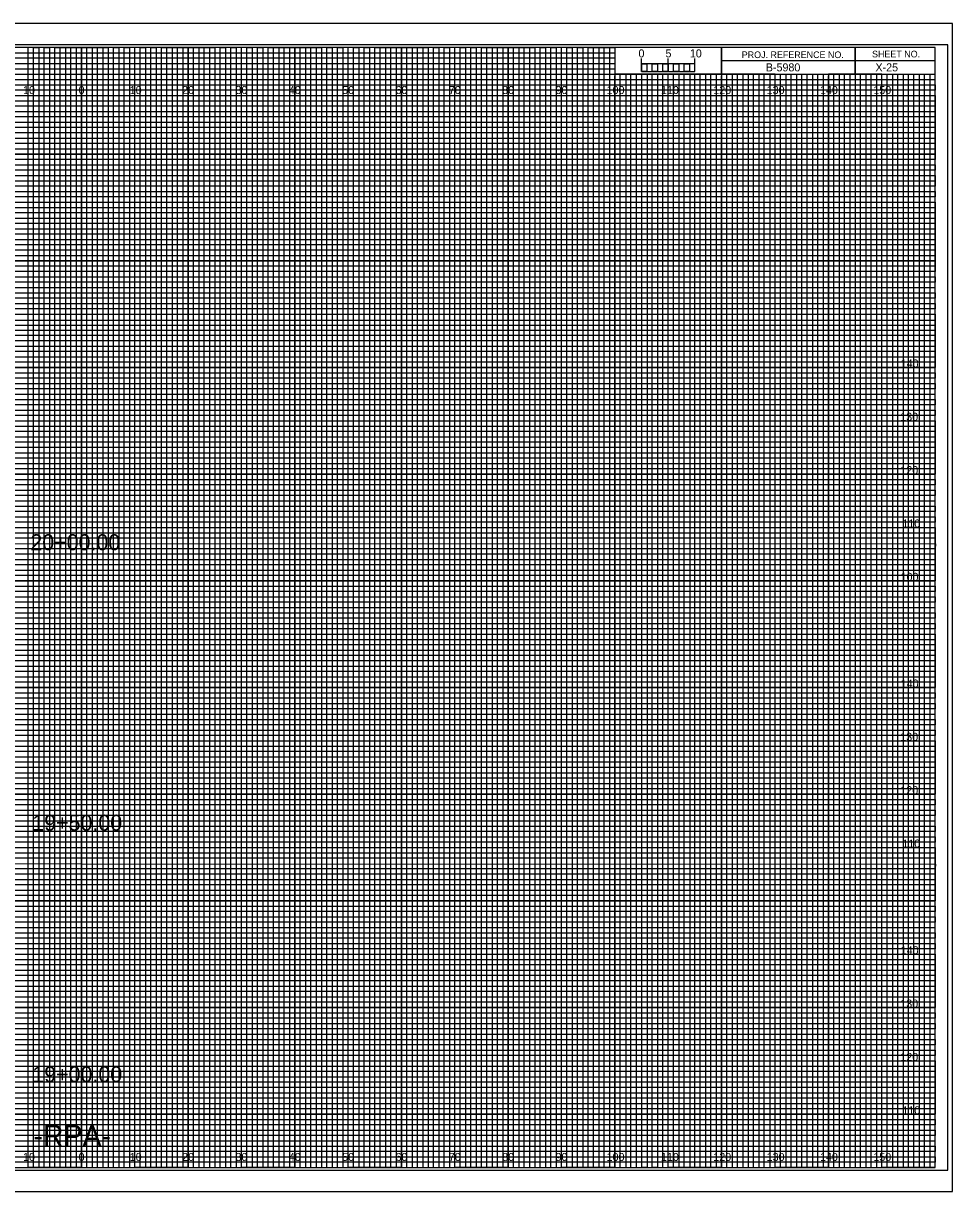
# Model space of a CAD drawing. Extents: x -13 to 323, y -5 to 1974.
# Drawn here: x 149.1 to 323.3, y 215.5 to 434.5 of the extents above; entities that cross this region are included whole.
import ezdxf

# ---------------------------------------------------------------- set-up
doc = ezdxf.new("R2010")
doc.units = 0
for name, color, linetype in [('Exist Cross Section Cell', 7, 'Continuous'), ('Exist XS Center Line Elevation Label', 7, 'Continuous'), ('Exist XS Ground Line', 7, 'Continuous'), ('Prop CMT Bridge Girder Bottom Critical Point Inside', 7, 'Continuous'), ('Prop CMT Guardrail Graphics', 7, 'Continuous'), ('Prop CMT Guardrail Widen Shoulder', 7, 'Continuous'), ('Prop CMT Pvmt Course 1', 7, 'Continuous'), ('Prop CMT Pvmt Course 2', 7, 'Continuous'), ('Prop CMT Pvmt Course 3', 7, 'Continuous'), ('Prop CMT Pvmt Surface', 7, 'Continuous'), ('Prop CMT Pvmt Surface Shoulder', 7, 'Continuous'), ('Prop CMT Shld Paved Course 1', 7, 'Continuous'), ('Prop CMT Shld Paved Course 2', 7, 'Continuous'), ('Prop CMT Shld Paved Course 3', 7, 'Continuous'), ('Prop CMT Slope Grass', 7, 'Continuous'), ('Prop CMT Subgrade Earthwork', 7, 'Continuous'), ('Scratch_Level_1', 7, 'Continuous')]:
    doc.layers.add(name, color=color, linetype=linetype)

msp = doc.modelspace()

# ---------------------------------------------------------------- linework, layer by layer
at = {"layer": 'Exist XS Center Line Elevation Label'}
for points in [[(145, 220), (155, 220), (155, 430), (165, 430), (165, 220), (175, 220), (175, 430), (185, 430), (185, 220), (195, 220), (195, 430), (205, 430), (205, 220), (215, 220), (215, 430), (225, 430), (225, 220), (235, 220), (235, 430), (245, 430), (245, 220), (255, 220), (255, 430), (259.93, 430), (260, 430), (260, 425), (264.99, 425), (264.99, 220), (275, 220), (275, 425), (285, 425), (285, 220), (295, 220), (295, 425), (305, 425), (305, 220), (315, 220), (315, 425)], [(0, 425), (275, 425)], [(0, 405), (320, 405), (320, 415), (0, 415)], [(0, 385), (320, 385), (320, 395), (0, 395)], [(0, 365), (320, 365), (320, 375), (0, 375)], [(0, 345), (320, 345), (320, 355), (0, 355)], [(0, 325), (320, 325), (320, 335), (0, 335)], [(0, 305), (320, 305), (320, 315), (0, 315)], [(0, 285), (320, 285), (320, 295), (0, 295)], [(0, 265), (320, 265), (320, 275), (0, 275)], [(0, 245), (320, 245), (320, 255), (0, 255)], [(0, 225), (320, 225), (320, 235), (0, 235)]]:
    msp.add_lwpolyline(points, dxfattribs=at)
at = {"layer": 'Exist XS Ground Line'}
for p, q in [((150, 430), (140, 430)), ((150, 220), (150, 430)), ((170, 430), (160, 430)), ((160, 430), (160, 220)), ((170, 220), (170, 430)), ((190, 430), (180, 430)), ((180, 430), (180, 220)), ((190, 220), (190, 430)), ((210, 430), (200, 430)), ((200, 430), (200, 220)), ((210, 220), (210, 430)), ((230, 430), (220, 430)), ((220, 430), (220, 220)), ((230, 220), (230, 430)), ((250, 430), (240, 430)), ((240, 430), (240, 220)), ((250, 220), (250, 430)), ((260, 430), (260, 220)), ((270, 220), (270, 425)), ((290, 425), (280, 425)), ((280, 425), (280, 220)), ((290, 220), (290, 425)), ((310, 425), (300, 425)), ((300, 425), (300, 220)), ((310, 220), (310, 425)), ((160, 220), (150, 220)), ((180, 220), (170, 220)), ((200, 220), (190, 220)), ((220, 220), (210, 220)), ((240, 220), (230, 220)), ((260, 220), (250, 220)), ((280, 220), (270, 220)), ((300, 220), (290, 220)), ((320, 220), (310, 220)), ((320, 220), (320, 220))]:
    msp.add_line(p, q, dxfattribs=at)
for points in [[(0, 420), (320, 420), (320, 410), (0, 410)], [(0, 400), (320, 400), (320, 390), (0, 390)], [(0, 380), (320, 380), (320, 370), (0, 370)], [(0, 360), (320, 360), (320, 350), (0, 350)], [(0, 340), (320, 340), (320, 330), (0, 330)], [(0, 320), (320, 320), (320, 310), (0, 310)], [(0, 300), (320, 300), (320, 290), (0, 290)], [(0, 280), (320, 280), (320, 270), (0, 270)], [(0, 260), (320, 260), (320, 250), (0, 250)], [(0, 240), (320, 240), (320, 230), (0, 230)]]:
    msp.add_lwpolyline(points, dxfattribs=at)
at = {"layer": 'Prop CMT Pvmt Course 2'}
for p, q in [((265, 425.49), (265, 427.9)), ((265, 426.9), (265, 427.9)), ((270, 425.49), (270, 427.9)), ((275, 425.49), (275, 427.9)), ((275, 426.9), (275, 427.9))]:
    msp.add_line(p, q, dxfattribs=at)
for points in [[(275, 426.9), (265, 426.9), (265, 425.49), (275, 425.49)], [(265, 426.9), (266, 426.9), (266, 425.49), (265, 425.49)], [(267, 426.9), (268, 426.9), (268, 425.49), (267, 425.49)], [(269, 426.9), (270, 426.9), (270, 425.49), (269, 425.49)], [(271, 426.9), (272, 426.9), (272, 425.49), (271, 425.49)], [(273, 426.9), (274, 426.9), (274, 425.49), (273, 425.49)]]:
    msp.add_lwpolyline(points, close=True, dxfattribs=at)
at = {"layer": 'Prop CMT Pvmt Course 3'}
msp.add_lwpolyline([(-13.4, 215.5), (323.3, 215.5), (323.3, 434.5), (-13.4, 434.5)], close=True, dxfattribs=at)
at = {"layer": 'Prop CMT Pvmt Surface'}
for p, q in [((150, 220), (150, 430)), ((160, 220), (160, 430)), ((170, 220), (170, 430)), ((180, 220), (180, 430)), ((190, 220), (190, 430)), ((200, 220), (200, 430)), ((210, 220), (210, 430)), ((220, 220), (220, 430)), ((230, 220), (230, 430)), ((240, 220), (240, 430)), ((250, 220), (250, 430)), ((260, 220), (260, 424.69)), ((270, 220), (270, 424.69)), ((280, 220), (280, 424.69)), ((290, 220), (290, 424.69)), ((300, 220), (300, 424.69)), ((310, 220), (310, 424.69)), ((0, 420), (320, 420)), ((0, 410), (320, 410)), ((0, 400), (320, 400)), ((0, 390), (320, 390)), ((0, 380), (320, 380)), ((0, 370), (320, 370)), ((0, 360), (320, 360)), ((0, 350), (320, 350)), ((0, 340), (320, 340)), ((0, 330), (320, 330)), ((0, 320), (320, 320)), ((0, 310), (320, 310)), ((0, 300), (320, 300)), ((0, 290), (320, 290)), ((0, 280), (320, 280)), ((0, 270), (320, 270)), ((0, 260), (320, 260)), ((0, 250), (320, 250)), ((0, 240), (320, 240)), ((0, 230), (320, 230))]:
    msp.add_line(p, q, dxfattribs=at)
at = {"layer": 'Prop CMT Pvmt Surface Shoulder'}
for p, q in [((323.3, 434.5), (-13.4, 434.5)), ((-13.4, 215.5), (323.3, 215.5))]:
    msp.add_line(p, q, dxfattribs=at)
at = {"layer": 'Prop CMT Shld Paved Course 1'}
for p, q in [((0, 429), (260, 429)), ((260, 427.98), (0, 427.98)), ((260, 429), (260, 427.98)), ((0, 427), (260, 427)), ((260, 425.89), (0, 425.89)), ((260, 427), (260, 425.89)), ((0, 424), (320, 424))]:
    msp.add_line(p, q, dxfattribs=at)
for points in [[(0, 423), (270, 423), (320, 423), (320, 422), (0, 422)], [(0, 421), (320, 421), (320, 419), (0, 419)], [(0, 418), (320, 418), (320, 417), (0, 416.98)], [(0, 416), (320, 416), (320, 414), (0, 414)], [(0, 413), (320, 413), (320, 412), (0, 412)], [(0, 411), (320, 411), (320, 409), (0, 409)], [(0, 408), (320, 408), (320, 407), (0, 407)], [(0, 406), (320, 406), (320, 404), (0, 404)], [(0, 403), (320, 403), (320, 402), (0, 402)], [(0, 401), (320, 401), (320, 399), (0, 399)], [(0, 398), (320, 398), (320, 397), (0, 397)], [(0, 396), (320, 396), (320, 393.95), (320, 393), (320, 392), (0, 392)], [(0, 394), (320, 394), (320, 393), (0, 393)], [(0, 391), (320, 391), (320, 389), (0, 389.03)], [(0, 389.03), (320, 389), (320, 388), (0, 388)], [(0, 387), (320, 387), (320, 386), (0, 386)], [(0, 384), (320, 384), (320, 383), (0, 383)], [(0, 382), (320, 382), (320, 381), (0, 381)], [(-0.07, 378.89), (320, 378.89), (320, 377.88), (-0.07, 377.88)], [(0, 377), (320, 377), (320, 376), (0, 376)], [(0, 374), (320, 374), (320, 373), (0, 373)], [(0, 372), (320, 372), (320, 371), (0, 371)], [(0, 369), (320, 369), (320, 368), (0, 368)], [(0, 367), (320, 367), (320, 366), (0, 366)], [(0, 364), (320, 364), (320, 363), (0, 363)], [(0, 362), (320, 362), (320, 361), (0, 361)], [(0, 359), (320, 359), (319.99, 357.98), (0, 358)], [(0, 357), (320, 357), (320, 356), (0, 356)], [(0, 354), (320, 354), (320, 353), (0, 353)], [(0, 352), (320, 352), (320, 351), (0, 351)], [(0, 349), (320, 349), (320, 348), (0, 348)], [(0, 347), (320, 347), (320, 346), (0, 346)], [(0, 344), (320, 344), (320, 343), (0, 343)], [(0, 342), (320, 342), (320, 341), (0, 341)], [(0, 339), (320, 339), (320, 338), (0, 338)], [(0, 336.99), (320.07, 336.91), (320, 336), (0, 336)], [(0, 334), (320, 334), (320, 333), (0, 333)], [(0, 332), (320, 332), (320, 331), (0, 331)], [(0, 329), (320, 329), (320, 328), (0, 328)], [(0, 327), (320, 327), (320, 326), (0, 326)], [(0, 324), (320, 324), (320, 323), (0, 323)], [(0, 322), (320, 322), (320, 321), (0, 321)], [(0, 319), (320, 319), (320, 318), (0, 318)], [(0, 317), (320, 317), (320, 316), (0, 316)], [(0, 314), (320, 314), (320, 313), (0, 313)], [(0, 312), (320, 312), (320, 311), (0, 311)], [(0, 309), (320, 309), (320, 308), (0, 308)], [(0, 307), (320, 307), (320, 306), (0, 306)], [(0, 304), (320, 304), (320, 303), (0, 303)], [(0, 302), (320, 302), (320, 301), (0, 301)], [(0, 299), (320, 299), (319.99, 297.98), (0, 298)], [(0, 297), (320, 297), (320, 296), (0, 296)], [(0, 294), (320, 294), (320, 293), (0, 293)], [(0, 292), (320, 292), (320, 291), (0, 291)], [(0, 289), (320, 289), (320, 288), (0, 288)], [(0, 287), (320, 287), (320, 286), (0, 286)], [(0, 284), (320, 284), (320, 283), (0, 283)], [(0, 282), (320, 282), (320, 281), (0, 281)], [(0, 279), (320, 279), (320, 278), (0, 278)], [(0, 276.99), (320.07, 276.91), (320, 276), (0, 276)], [(0, 274), (320, 274), (320, 273), (0, 273)], [(0, 272), (320, 272), (320, 271), (0, 271)], [(0, 269), (320, 269), (320, 268), (0, 268)], [(0, 267), (320, 267), (320, 266), (0, 266)], [(0, 264), (320, 264), (320, 263), (0, 263)], [(0, 262), (320, 262), (320, 261), (0, 261)], [(0, 259), (320, 259), (320, 258), (0, 258)], [(0, 257), (320, 257), (320, 256), (0, 256)], [(0, 254), (320, 254), (320, 253), (0, 253)], [(0, 252), (320, 252), (320, 251), (0, 251)], [(0, 249), (320, 249), (320, 248), (0, 248)], [(0, 247), (320, 247), (320, 246), (0, 246)], [(0, 244), (320, 244), (320, 243), (0, 243)], [(0, 242), (320, 242), (320, 241), (0, 241)], [(0, 239), (320, 239), (320, 238), (0, 238)], [(0, 237), (320, 237), (320, 236), (0, 236)], [(0, 234), (320, 234), (320, 233), (0, 233)], [(0, 232), (320, 232), (320, 231), (0, 231)], [(0, 229), (320, 229), (320, 228), (0, 228)], [(0, 227), (320, 227), (320, 226), (0, 226)], [(0, 224), (320, 224), (320, 223), (0, 223)], [(0, 222), (320, 222), (320, 221), (0, 221)]]:
    msp.add_lwpolyline(points, dxfattribs=at)
at = {"layer": 'Prop CMT Shld Paved Course 2'}
for p, q in [((305, 430), (305, 425)), ((305, 425), (305, 430)), ((280, 427.5), (280, 425)), ((320, 427.49), (280, 427.49)), ((280, 425), (320, 425))]:
    msp.add_line(p, q, dxfattribs=at)
for points in [[(320, 430), (0, 430), (0, 220), (320, 220)], [(280, 430), (260, 430), (260, 425.03), (280, 425.03)], [(320, 430), (280, 430), (280, 425), (320, 425)]]:
    msp.add_lwpolyline(points, close=True, dxfattribs=at)
at = {"layer": 'Prop CMT Shld Paved Course 3'}
for p, q in [((267, 425), (266.01, 425)), ((266.01, 425), (266.01, 220)), ((267, 220), (267, 425)), ((269, 425), (268, 425)), ((268, 425), (268, 220)), ((269, 220), (269, 425)), ((266.01, 220), (265, 220)), ((268, 220), (267, 220))]:
    msp.add_line(p, q, dxfattribs=at)
for points in [[(150, 220), (151, 220), (151, 430), (152, 430), (152, 220)], [(152, 220), (153, 220), (153, 430), (154, 430), (154, 220)], [(155, 220), (156, 220), (156, 430), (157, 430), (157, 220)], [(157, 220), (158, 220), (158, 430), (159, 430), (159, 220)], [(160, 220), (161, 220), (161, 430), (162, 430), (162, 220)], [(162, 220), (163, 220), (163, 430), (164, 430), (164, 220)], [(165, 220), (166, 220), (166, 430), (167, 430), (167, 220)], [(167, 220), (168, 220), (168, 430), (169, 430), (169, 220)], [(170, 220), (171, 220), (171, 430), (172, 430), (172, 220)], [(172, 220), (173, 220), (173, 430), (174, 430), (174, 220)], [(175, 220), (176, 220), (176, 430), (177, 430), (177, 220)], [(177, 220), (178, 220), (178, 430), (179, 430), (179, 220)], [(180, 220), (181, 220), (181, 430), (182, 430), (182, 220)], [(182, 220), (183, 220), (183, 430), (184, 430), (184, 220)], [(185, 220), (186, 220), (186, 430), (187, 430), (187, 220)], [(187, 220), (188, 220), (188, 430), (189, 430), (189, 220)], [(190, 220), (191, 220), (191, 430), (192, 430), (192, 220)], [(192, 220), (193, 220), (193, 430), (194, 430), (194, 220)], [(195, 220), (196, 220), (196, 430), (197, 430), (197, 220)], [(197, 220), (198, 220), (198, 430), (199, 430), (199, 220)], [(200, 220), (201, 220), (201, 430), (202, 430), (202, 220)], [(202, 220), (203, 220), (203, 430), (204, 430), (204, 220)], [(205, 220), (206, 220), (206, 430), (207, 430), (207, 220)], [(207, 220), (208, 220), (208, 430), (209, 430), (209, 220)], [(210, 220), (211, 220), (211, 430), (212, 430), (212, 220)], [(212, 220), (213, 220), (213, 430), (214, 430), (214, 220)], [(215, 220), (216, 220), (216, 430), (217, 430), (217, 220)], [(217, 220), (218, 220), (218, 430), (219, 430), (219, 220)], [(220, 220), (221, 220), (221, 430), (222, 430), (222, 220)], [(222, 220), (223, 220), (223, 430), (224, 430), (224, 220)], [(225, 220), (226, 220), (226, 430), (227, 430), (227, 220)], [(227, 220), (228, 220), (228, 430), (229, 430), (229, 220)], [(230, 220), (231, 220), (231, 430), (232, 430), (232, 220)], [(232, 220), (233, 220), (233, 430), (234, 430), (234, 220)], [(235, 220), (236, 220), (236, 430), (237, 430), (237, 220)], [(237, 220), (238, 220), (238, 430), (239, 430), (239, 220)], [(240, 220), (241, 220), (241, 430), (242, 430), (242, 220)], [(242, 220), (243, 220), (243, 430), (244, 430), (244, 220)], [(245, 220), (246, 220), (246, 430), (247, 430), (247, 220)], [(247, 220), (248, 220), (248, 430), (249, 430), (249, 220)], [(250, 220), (251, 220), (251, 430), (252, 430), (252, 220)], [(252, 220), (253, 220), (253, 430), (254, 430), (254, 220)], [(255, 220), (256, 220), (256, 430), (257, 430), (257, 220)], [(257, 220), (258, 220), (258, 430), (259, 430), (259, 220)], [(260, 220), (261, 220), (261, 425), (262.02, 425), (262.02, 220)], [(262, 220), (263, 220), (263, 425), (263.99, 425), (263.99, 220)], [(270, 220), (270.98, 220), (270.98, 425), (272, 425), (272, 220)], [(272, 220), (273, 220), (273, 425), (274.05, 425), (274.05, 220)], [(275, 220), (276, 220), (276, 425), (277, 425), (277, 220)], [(277, 220), (278, 220), (278, 425), (279, 425), (279, 220)], [(280, 220), (281, 220), (281, 425), (282, 425), (282, 220)], [(282, 220), (283, 220), (283, 425), (284, 425), (284, 220)], [(285, 220), (286, 220), (286, 425), (287, 425), (287, 220)], [(287, 220), (288, 220), (288, 425), (289, 425), (289, 220)], [(290, 220), (291, 220), (291, 425), (292, 425), (292, 220)], [(292, 220), (293, 220), (293, 425), (294, 425), (294, 220)], [(295, 220), (296, 220), (296, 425), (297, 425), (297, 220)], [(297, 220), (298, 220), (298, 425), (299, 425), (299, 220)], [(300, 220), (301, 220), (301, 425), (302, 425), (302, 220)], [(302, 220), (303, 220), (303, 425), (304, 425), (304, 220)], [(305, 220), (306, 220), (306, 425), (307, 425), (307, 220)], [(307, 220), (308, 220), (308, 425), (309, 425), (309, 220)], [(310, 220), (311, 220), (311, 425), (312, 425), (312, 220)], [(312, 220), (313, 220), (313, 425), (314, 425), (314, 220)], [(315, 220), (316, 220), (316, 425), (317, 425), (317, 220)], [(317, 220), (318, 220), (318, 425), (319, 425), (319, 220)]]:
    msp.add_lwpolyline(points, dxfattribs=at)
at = {"layer": 'Prop CMT Subgrade Earthwork'}
msp.add_lwpolyline([(-10.8, 219.5), (322.4, 219.5), (322.4, 430.5), (-10.8, 430.5)], close=True, dxfattribs=at)

# ---------------------------------------------------------------- texts
at = {"layer": 'Exist Cross Section Cell'}
for s, p in [('10', (149.04, 421.25)), ('0', (159.45, 421.25)), ('0', (159.45, 421.25)), ('10', (169.04, 421.25)), ('20', (178.86, 421.25)), ('30', (188.86, 421.25)), ('40', (198.86, 421.25)), ('50', (208.86, 421.25)), ('60', (218.86, 421.25)), ('70', (228.86, 421.25)), ('80', (238.86, 421.25)), ('90', (248.86, 421.25)), ('100', (258.44, 421.25)), ('110', (268.62, 421.25)), ('120', (278.44, 421.25)), ('130', (288.44, 421.25)), ('140', (298.44, 421.25)), ('150', (308.44, 421.25)), ('10', (149.04, 221.25)), ('0', (159.45, 221.25)), ('0', (159.45, 221.25)), ('10', (169.04, 221.25)), ('20', (178.86, 221.25)), ('30', (188.86, 221.25)), ('40', (198.86, 221.25)), ('50', (208.86, 221.25)), ('60', (218.86, 221.25)), ('70', (228.86, 221.25)), ('80', (238.86, 221.25)), ('90', (248.86, 221.25)), ('100', (258.44, 221.25)), ('110', (268.62, 221.25)), ('120', (278.44, 221.25)), ('130', (288.44, 221.25)), ('140', (298.44, 221.25)), ('150', (308.44, 221.25))]:
    msp.add_text(s, height=1.5, dxfattribs=at).set_placement(p)
at = {"layer": 'Prop CMT Bridge Girder Bottom Critical Point Inside'}
for s, p in [('5', (269.47, 428.12)), ('10', (274.04, 428.12))]:
    msp.add_text(s, height=1.5, dxfattribs=at).set_placement(p)
at = {"layer": 'Prop CMT Guardrail Graphics'}
msp.add_text('B-5980', height=1.5, dxfattribs=at).set_placement((288.28, 425.5))
at = {"layer": 'Prop CMT Guardrail Widen Shoulder'}
msp.add_text('X-25', height=1.5, dxfattribs=at).set_placement((308.83, 425.5))
at = {"layer": 'Prop CMT Pvmt Course 1'}
for s, p in [('140', (313.57, 370)), ('130', (313.49, 360)), ('120', (313.5, 350)), ('110', (313.88, 340)), ('100', (313.55, 330)), ('140', (313.57, 310)), ('130', (313.49, 300)), ('120', (313.5, 290)), ('110', (313.88, 280)), ('140', (313.57, 260)), ('130', (313.49, 250)), ('120', (313.5, 240)), ('110', (313.88, 230))]:
    msp.add_text(s, height=1.5, dxfattribs=at).set_placement(p)
at = {"layer": 'Prop CMT Pvmt Course 2'}
msp.add_text('0', height=1.5, dxfattribs=at).set_placement((264.41, 428.12))
at = {"layer": 'Prop CMT Shld Paved Course 2'}
for s, p in [('PROJ. REFERENCE NO.', (283.77, 427.99)), ('SHEET NO.', (308.19, 428.12))]:
    msp.add_text(s, height=1.25, dxfattribs=at).set_placement(p)
at = {"layer": 'Prop CMT Slope Grass'}
for s, p in [('20+00.00', (150.41, 335.73)), ('19+50.00', (150.77, 283.16)), ('19+00.00', (150.77, 236))]:
    msp.add_text(s, height=3, dxfattribs=at).set_placement(p)
at = {"layer": 'Scratch_Level_1'}
msp.add_text('-RPA-', height=4, dxfattribs=at).set_placement((150.97, 224))

doc.saveas('drawing.dxf')
